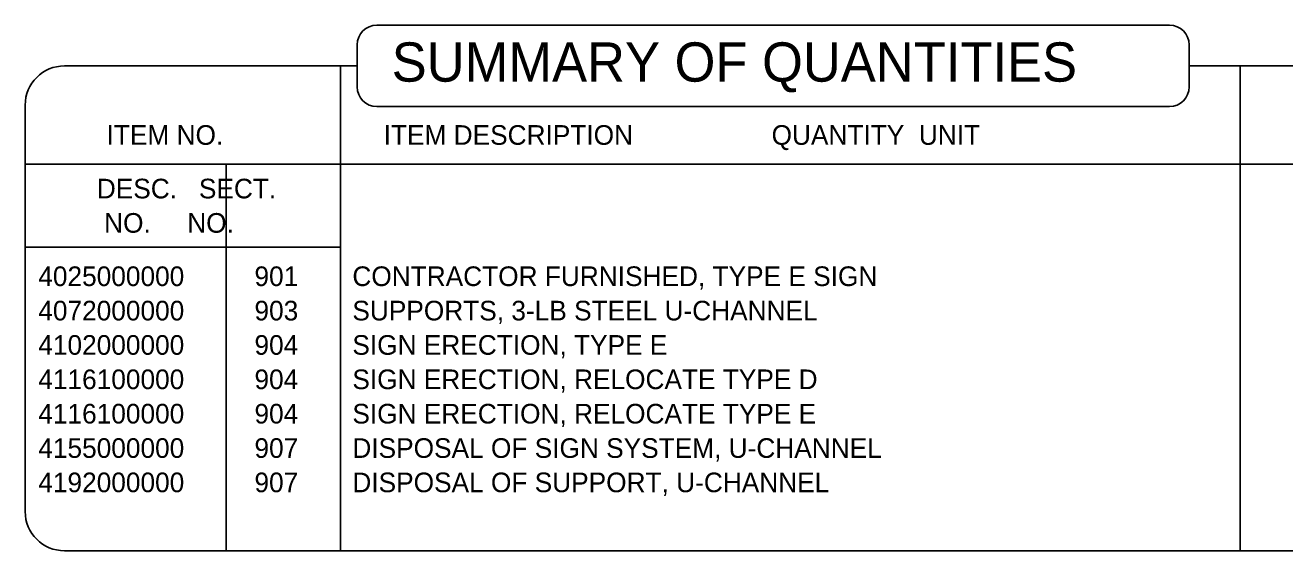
# Model space of a CAD drawing. Extents: x 2046816 to 2049224, y 578750 to 586986.
# Drawn here: x 2047904.2 to 2048289.2, y 586214.8 to 586375.4 of the extents above; entities that cross this region are included whole.
import ezdxf

# ---------------------------------------------------------------- set-up
doc = ezdxf.new("R2010")
doc.units = 0
doc.layers.add('Default', color=7, linetype='Continuous')
doc.layers.add('Sheet Title CELL', color=7, linetype='Continuous')

msp = doc.modelspace()

# ---------------------------------------------------------------- linework, layer by layer
at = {"layer": 'Default'}
for p, q in [((2048000.56, 586362.96), (2048000.56, 586214.83)), ((2048275.55, 586362.96), (2048275.55, 586214.83)), ((2047904.15, 586332.97), (2048361.44, 586332.97)), ((2047965.64, 586332.97), (2047965.64, 586214.83)), ((2047904.15, 586307.53), (2048000.56, 586307.53))]:
    msp.add_line(p, q, dxfattribs=at)
at = {"layer": 'Sheet Title CELL'}
for p, q in [((2048011.64, 586375.38), (2048253.96, 586375.38)), ((2048005.64, 586369.38), (2048005.64, 586356.53)), ((2048259.96, 586369.38), (2048259.96, 586356.53)), ((2047916.15, 586362.96), (2048005.64, 586362.96)), ((2048259.96, 586362.96), (2048349.44, 586362.96)), ((2047904.15, 586350.96), (2047904.15, 586226.83)), ((2048253.96, 586350.53), (2048011.64, 586350.53)), ((2047916.15, 586214.83), (2048349.44, 586214.83))]:
    msp.add_line(p, q, dxfattribs=at)
for centre, radius, start, end in [((2048011.64, 586369.38), 6, 90, 180), ((2048253.96, 586369.38), 6, 360, 90), ((2047916.15, 586350.96), 12, 90, 180), ((2048011.64, 586356.53), 6, 180, 270), ((2048253.96, 586356.53), 6, 270, 0), ((2047916.15, 586226.83), 12, 180, 270)]:
    msp.add_arc(centre, radius, start, end, dxfattribs=at)

# ---------------------------------------------------------------- texts
at = {"layer": 'Default'}
for s, height, p in [('SUMMARY OF QUANTITIES', 12, (2048016.19, 586358.14)), ('ITEM NO.                      ITEM DESCRIPTION                   QUANTITY  UNIT', 6, (2047929.04, 586338.85)), ('DESC.   SECT.', 6, (2047926.05, 586322.48)), (' NO.     NO.', 6, (2047926.05, 586311.99)), ('4025000000', 6, (2047908.16, 586295.7)), ('901', 6, (2047974.24, 586295.7)), ('CONTRACTOR FURNISHED, TYPE E SIGN ', 6, (2048004.17, 586295.7)), ('4072000000', 6, (2047908.16, 586285.2)), ('903', 6, (2047974.24, 586285.2)), ('SUPPORTS, 3-LB STEEL U-CHANNEL', 6, (2048004.17, 586285.2)), ('4102000000', 6, (2047908.16, 586274.71)), ('904', 6, (2047974.24, 586274.71)), ('SIGN ERECTION, TYPE E', 6, (2048004.17, 586274.71)), ('4116100000', 6, (2047908.16, 586264.21)), ('904', 6, (2047974.24, 586264.21)), ('SIGN ERECTION, RELOCATE TYPE D', 6, (2048004.17, 586264.21)), ('4116100000', 6, (2047908.16, 586253.71)), ('904', 6, (2047974.24, 586253.71)), ('SIGN ERECTION, RELOCATE TYPE E', 6, (2048004.17, 586253.71)), ('4155000000', 6, (2047908.16, 586243.21)), ('907', 6, (2047974.24, 586243.21)), ('DISPOSAL OF SIGN SYSTEM, U-CHANNEL', 6, (2048004.17, 586243.21)), ('4192000000', 6, (2047908.16, 586232.72)), ('907', 6, (2047974.24, 586232.72)), ('DISPOSAL OF SUPPORT, U-CHANNEL', 6, (2048004.17, 586232.72))]:
    msp.add_text(s, height=height, dxfattribs=at).set_placement(p)

doc.saveas('drawing.dxf')
